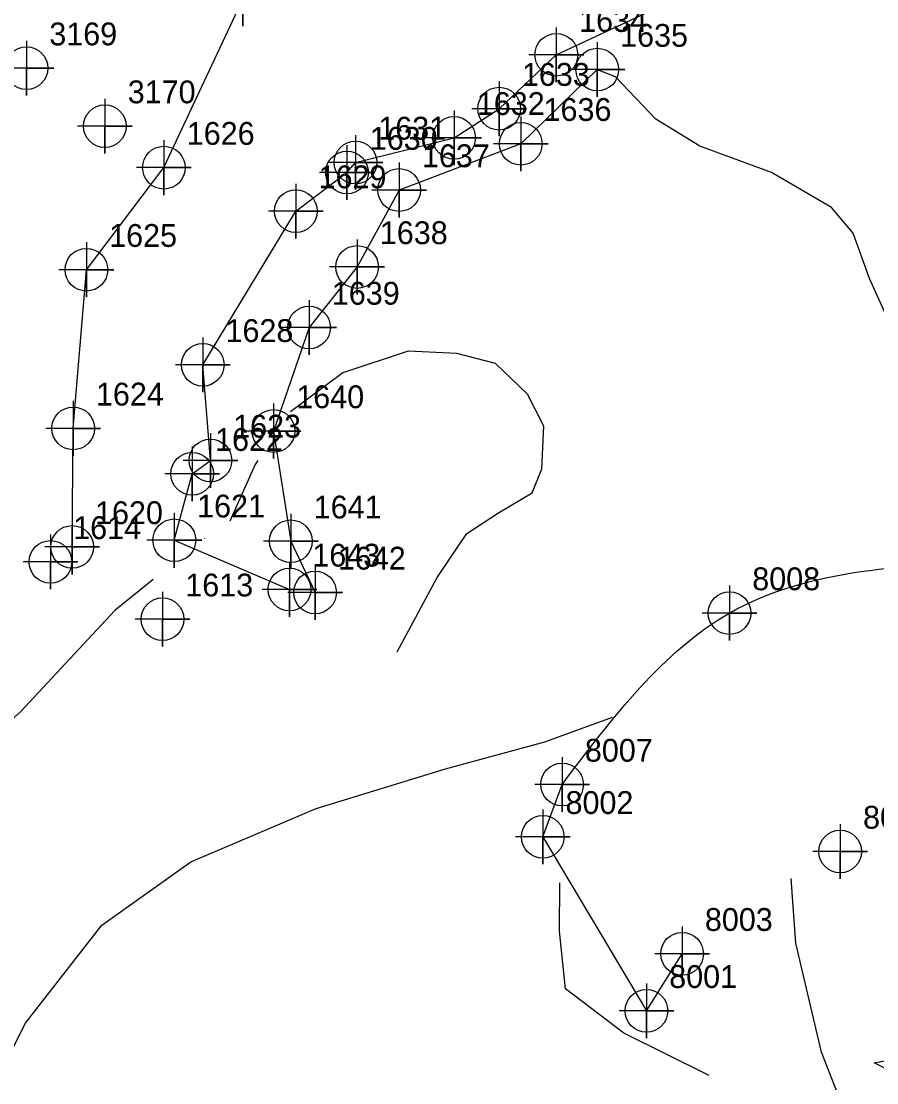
# Model space of a CAD drawing. Extents: x 2062781 to 2066835, y 358981 to 366501.
# Drawn here: x 2064156.3 to 2064250, y 361856.4 to 361972.7 of the extents above; entities that cross this region are included whole.
import ezdxf

# ---------------------------------------------------------------- set-up
doc = ezdxf.new("R2010")
doc.units = 0
for name, color, linetype in [('Exist Building Cogo Number', 7, 'Continuous'), ('Exist Building Cogo Point CELL', 7, 'Continuous'), ('Exist DTM Breakline', 7, 'Continuous'), ('Exist DTM Breakline Cogo Number', 7, 'Continuous'), ('Exist DTM Breakline Cogo Point CELL', 7, 'Continuous'), ('Exist DTM Regular Point CELL', 7, 'Continuous'), ('Exist DTM Regular Point Cogo Number', 7, 'Continuous'), ('Exist DTM Ridgeline', 7, 'Continuous'), ('Exist DTM Ridgeline Cogo Number', 7, 'Continuous'), ('Exist DTM Ridgeline Cogo Point CELL', 7, 'Continuous'), ('PH Exist DTM Breakline', 7, 'Continuous'), ('PH Exist DTM Point', 7, 'Continuous')]:
    doc.layers.add(name, color=color, linetype=linetype)

msp = doc.modelspace()

# ---------------------------------------------------------------- linework, layer by layer
at = {"layer": 'Exist Building Cogo Point CELL'}
for points in [[(2064233.88, 361910.89), (2064233.88, 361904.89), (2064233.88, 361907.89), (2064236.88, 361907.89), (2064230.88, 361907.89)], [(2064233.88, 361910.89), (2064233.88, 361904.89), (2064233.88, 361907.89), (2064236.88, 361907.89), (2064230.88, 361907.89)], [(2064233.88, 361910.89), (2064233.88, 361904.89), (2064233.88, 361907.89), (2064236.88, 361907.89), (2064230.88, 361907.89)], [(2064215.54, 361892.11), (2064215.54, 361886.11), (2064215.54, 361889.11), (2064218.54, 361889.11), (2064212.54, 361889.11)], [(2064215.54, 361892.11), (2064215.54, 361886.11), (2064215.54, 361889.11), (2064218.54, 361889.11), (2064212.54, 361889.11)], [(2064215.54, 361892.11), (2064215.54, 361886.11), (2064215.54, 361889.11), (2064218.54, 361889.11), (2064212.54, 361889.11)], [(2064213.42, 361886.38), (2064213.42, 361880.38), (2064213.42, 361883.38), (2064216.42, 361883.38), (2064210.42, 361883.38)], [(2064213.42, 361886.38), (2064213.42, 361880.38), (2064213.42, 361883.38), (2064216.42, 361883.38), (2064210.42, 361883.38)], [(2064213.42, 361886.38), (2064213.42, 361880.38), (2064213.42, 361883.38), (2064216.42, 361883.38), (2064210.42, 361883.38)], [(2064246.02, 361884.77), (2064246.02, 361878.77), (2064246.02, 361881.77), (2064249.02, 361881.77), (2064243.02, 361881.77)], [(2064246.02, 361884.77), (2064246.02, 361878.77), (2064246.02, 361881.77), (2064249.02, 361881.77), (2064243.02, 361881.77)], [(2064246.02, 361884.77), (2064246.02, 361878.77), (2064246.02, 361881.77), (2064249.02, 361881.77), (2064243.02, 361881.77)], [(2064228.69, 361873.57), (2064228.69, 361867.57), (2064228.69, 361870.57), (2064231.69, 361870.57), (2064225.69, 361870.57)], [(2064228.69, 361873.57), (2064228.69, 361867.57), (2064228.69, 361870.57), (2064231.69, 361870.57), (2064225.69, 361870.57)], [(2064228.69, 361873.57), (2064228.69, 361867.57), (2064228.69, 361870.57), (2064231.69, 361870.57), (2064225.69, 361870.57)], [(2064224.78, 361867.32), (2064224.78, 361861.32), (2064224.78, 361864.32), (2064227.78, 361864.32), (2064221.78, 361864.32)], [(2064224.78, 361867.32), (2064224.78, 361861.32), (2064224.78, 361864.32), (2064227.78, 361864.32), (2064221.78, 361864.32)], [(2064224.78, 361867.32), (2064224.78, 361861.32), (2064224.78, 361864.32), (2064227.78, 361864.32), (2064221.78, 361864.32)]]:
    msp.add_lwpolyline(points, dxfattribs=at)
for centre in [(2064233.88, 361907.89), (2064233.88, 361907.89), (2064233.88, 361907.89), (2064215.54, 361889.11), (2064215.54, 361889.11), (2064215.54, 361889.11), (2064213.42, 361883.38), (2064213.42, 361883.38), (2064213.42, 361883.38), (2064246.02, 361881.77), (2064246.02, 361881.77), (2064246.02, 361881.77), (2064228.69, 361870.57), (2064228.69, 361870.57), (2064228.69, 361870.57), (2064224.78, 361864.32), (2064224.78, 361864.32), (2064224.78, 361864.32)]:
    msp.add_circle(centre, 2.34, dxfattribs=at)
at = {"layer": 'Exist DTM Breakline'}
for p, q in [((2064214.91, 361969.05), (2064225.1, 361973.79)), ((2064213.42, 361883.38), (2064215.54, 361889.11)), ((2064224.78, 361864.32), (2064228.69, 361870.57))]:
    msp.add_line(p, q, dxfattribs=at)
for points in [[(2064173.05, 361915.86), (2064175.01, 361923.15), (2064177, 361924.61), (2064176.16, 361935.08), (2064186.36, 361951.92), (2064191.97, 361956.14), (2064192.9, 361957.25), (2064203.7, 361959.95), (2064208.64, 361963.14), (2064214.91, 361969.05)], [(2064173.05, 361915.86), (2064185.67, 361910.48)], [(2064213.42, 361883.38), (2064224.78, 361864.32)]]:
    msp.add_lwpolyline(points, dxfattribs=at)
msp.add_spline([(2064215.54, 361889.11), (2064233.88, 361907.89), (2064264.5, 361913.6)], degree=3, dxfattribs=at)
at = {"layer": 'Exist DTM Breakline Cogo Point CELL'}
for points in [[(2064214.91, 361972.05), (2064214.91, 361966.05), (2064214.91, 361969.05), (2064217.91, 361969.05), (2064211.91, 361969.05)], [(2064214.91, 361972.05), (2064214.91, 361966.05), (2064214.91, 361969.05), (2064217.91, 361969.05), (2064211.91, 361969.05)], [(2064214.91, 361972.05), (2064214.91, 361966.05), (2064214.91, 361969.05), (2064217.91, 361969.05), (2064211.91, 361969.05)], [(2064208.64, 361966.14), (2064208.64, 361960.14), (2064208.64, 361963.14), (2064211.64, 361963.14), (2064205.64, 361963.14)], [(2064208.64, 361966.14), (2064208.64, 361960.14), (2064208.64, 361963.14), (2064211.64, 361963.14), (2064205.64, 361963.14)], [(2064208.64, 361966.14), (2064208.64, 361960.14), (2064208.64, 361963.14), (2064211.64, 361963.14), (2064205.64, 361963.14)], [(2064203.7, 361962.95), (2064203.7, 361956.95), (2064203.7, 361959.95), (2064206.7, 361959.95), (2064200.7, 361959.95)], [(2064203.7, 361962.95), (2064203.7, 361956.95), (2064203.7, 361959.95), (2064206.7, 361959.95), (2064200.7, 361959.95)], [(2064203.7, 361962.95), (2064203.7, 361956.95), (2064203.7, 361959.95), (2064206.7, 361959.95), (2064200.7, 361959.95)], [(2064192.9, 361960.25), (2064192.9, 361954.25), (2064192.9, 361957.25), (2064195.9, 361957.25), (2064189.9, 361957.25)], [(2064192.9, 361960.25), (2064192.9, 361954.25), (2064192.9, 361957.25), (2064195.9, 361957.25), (2064189.9, 361957.25)], [(2064192.9, 361960.25), (2064192.9, 361954.25), (2064192.9, 361957.25), (2064195.9, 361957.25), (2064189.9, 361957.25)], [(2064191.97, 361959.14), (2064191.97, 361953.14), (2064191.97, 361956.14), (2064194.97, 361956.14), (2064188.97, 361956.14)], [(2064191.97, 361959.14), (2064191.97, 361953.14), (2064191.97, 361956.14), (2064194.97, 361956.14), (2064188.97, 361956.14)], [(2064191.97, 361959.14), (2064191.97, 361953.14), (2064191.97, 361956.14), (2064194.97, 361956.14), (2064188.97, 361956.14)], [(2064186.36, 361954.92), (2064186.36, 361948.92), (2064186.36, 361951.92), (2064189.36, 361951.92), (2064183.36, 361951.92)], [(2064186.36, 361954.92), (2064186.36, 361948.92), (2064186.36, 361951.92), (2064189.36, 361951.92), (2064183.36, 361951.92)], [(2064186.36, 361954.92), (2064186.36, 361948.92), (2064186.36, 361951.92), (2064189.36, 361951.92), (2064183.36, 361951.92)], [(2064176.16, 361938.08), (2064176.16, 361932.08), (2064176.16, 361935.08), (2064179.16, 361935.08), (2064173.16, 361935.08)], [(2064176.16, 361938.08), (2064176.16, 361932.08), (2064176.16, 361935.08), (2064179.16, 361935.08), (2064173.16, 361935.08)], [(2064176.16, 361938.08), (2064176.16, 361932.08), (2064176.16, 361935.08), (2064179.16, 361935.08), (2064173.16, 361935.08)], [(2064177, 361927.61), (2064177, 361921.61), (2064177, 361924.61), (2064180, 361924.61), (2064174, 361924.61)], [(2064177, 361927.61), (2064177, 361921.61), (2064177, 361924.61), (2064180, 361924.61), (2064174, 361924.61)], [(2064177, 361927.61), (2064177, 361921.61), (2064177, 361924.61), (2064180, 361924.61), (2064174, 361924.61)], [(2064175.01, 361926.15), (2064175.01, 361920.15), (2064175.01, 361923.15), (2064178.01, 361923.15), (2064172.01, 361923.15)], [(2064175.01, 361926.15), (2064175.01, 361920.15), (2064175.01, 361923.15), (2064178.01, 361923.15), (2064172.01, 361923.15)], [(2064175.01, 361926.15), (2064175.01, 361920.15), (2064175.01, 361923.15), (2064178.01, 361923.15), (2064172.01, 361923.15)], [(2064173.05, 361918.86), (2064173.05, 361912.86), (2064173.05, 361915.86), (2064176.05, 361915.86), (2064170.05, 361915.86)], [(2064173.05, 361918.86), (2064173.05, 361912.86), (2064173.05, 361915.86), (2064176.05, 361915.86), (2064170.05, 361915.86)], [(2064173.05, 361918.86), (2064173.05, 361912.86), (2064173.05, 361915.86), (2064176.05, 361915.86), (2064170.05, 361915.86)], [(2064185.67, 361913.48), (2064185.67, 361907.48), (2064185.67, 361910.48), (2064188.67, 361910.48), (2064182.67, 361910.48)], [(2064185.67, 361913.48), (2064185.67, 361907.48), (2064185.67, 361910.48), (2064188.67, 361910.48), (2064182.67, 361910.48)], [(2064185.67, 361913.48), (2064185.67, 361907.48), (2064185.67, 361910.48), (2064188.67, 361910.48), (2064182.67, 361910.48)]]:
    msp.add_lwpolyline(points, dxfattribs=at)
for centre in [(2064214.91, 361969.05), (2064214.91, 361969.05), (2064214.91, 361969.05), (2064208.64, 361963.14), (2064208.64, 361963.14), (2064208.64, 361963.14), (2064203.7, 361959.95), (2064203.7, 361959.95), (2064203.7, 361959.95), (2064192.9, 361957.25), (2064192.9, 361957.25), (2064192.9, 361957.25), (2064191.97, 361956.14), (2064191.97, 361956.14), (2064191.97, 361956.14), (2064186.36, 361951.92), (2064186.36, 361951.92), (2064186.36, 361951.92), (2064176.16, 361935.08), (2064176.16, 361935.08), (2064176.16, 361935.08), (2064177, 361924.61), (2064177, 361924.61), (2064177, 361924.61), (2064175.01, 361923.15), (2064175.01, 361923.15), (2064175.01, 361923.15), (2064173.05, 361915.86), (2064173.05, 361915.86), (2064173.05, 361915.86), (2064185.67, 361910.48), (2064185.67, 361910.48), (2064185.67, 361910.48)]:
    msp.add_circle(centre, 2.34, dxfattribs=at)
at = {"layer": 'Exist DTM Regular Point CELL'}
for points in [[(2064156.85, 361970.58), (2064156.85, 361964.58), (2064156.85, 361967.58), (2064159.85, 361967.58), (2064153.85, 361967.58)], [(2064165.44, 361964.23), (2064165.44, 361958.23), (2064165.44, 361961.23), (2064168.44, 361961.23), (2064162.44, 361961.23)], [(2064159.47, 361916.49), (2064159.47, 361910.49), (2064159.47, 361913.49), (2064162.47, 361913.49), (2064156.47, 361913.49)], [(2064171.75, 361910.21), (2064171.75, 361904.21), (2064171.75, 361907.21), (2064174.75, 361907.21), (2064168.75, 361907.21)]]:
    msp.add_lwpolyline(points, dxfattribs=at)
for centre in [(2064156.85, 361967.58), (2064165.44, 361961.23), (2064159.47, 361913.49), (2064171.75, 361907.21)]:
    msp.add_circle(centre, 2.34, dxfattribs=at)
at = {"layer": 'Exist DTM Ridgeline'}
msp.add_line((2064219.4, 361967.42), (2064221.37, 361966.68), dxfattribs=at)
for points in [[(2064171.91, 361956.68), (2064180.57, 361975.17)], [(2064219.4, 361967.42), (2064211.01, 361959.3), (2064197.68, 361954.23), (2064193.07, 361945.8), (2064187.81, 361939.17), (2064183.91, 361927.83), (2064185.82, 361915.75), (2064188.47, 361910.15)], [(2064161.86, 361915.13), (2064161.96, 361928.12), (2064163.41, 361945.5), (2064171.91, 361956.68)]]:
    msp.add_lwpolyline(points, dxfattribs=at)
at = {"layer": 'Exist DTM Ridgeline Cogo Point CELL'}
for points in [[(2064180.57, 361978.17), (2064180.57, 361972.17), (2064180.57, 361975.17), (2064183.57, 361975.17), (2064177.57, 361975.17)], [(2064180.57, 361978.17), (2064180.57, 361972.17), (2064180.57, 361975.17), (2064183.57, 361975.17), (2064177.57, 361975.17)], [(2064180.57, 361978.17), (2064180.57, 361972.17), (2064180.57, 361975.17), (2064183.57, 361975.17), (2064177.57, 361975.17)], [(2064219.4, 361970.42), (2064219.4, 361964.42), (2064219.4, 361967.42), (2064222.4, 361967.42), (2064216.4, 361967.42)], [(2064219.4, 361970.42), (2064219.4, 361964.42), (2064219.4, 361967.42), (2064222.4, 361967.42), (2064216.4, 361967.42)], [(2064219.4, 361970.42), (2064219.4, 361964.42), (2064219.4, 361967.42), (2064222.4, 361967.42), (2064216.4, 361967.42)], [(2064211.01, 361962.3), (2064211.01, 361956.3), (2064211.01, 361959.3), (2064214.01, 361959.3), (2064208.01, 361959.3)], [(2064211.01, 361962.3), (2064211.01, 361956.3), (2064211.01, 361959.3), (2064214.01, 361959.3), (2064208.01, 361959.3)], [(2064211.01, 361962.3), (2064211.01, 361956.3), (2064211.01, 361959.3), (2064214.01, 361959.3), (2064208.01, 361959.3)], [(2064171.91, 361959.68), (2064171.91, 361953.68), (2064171.91, 361956.68), (2064174.91, 361956.68), (2064168.91, 361956.68)], [(2064171.91, 361959.68), (2064171.91, 361953.68), (2064171.91, 361956.68), (2064174.91, 361956.68), (2064168.91, 361956.68)], [(2064171.91, 361959.68), (2064171.91, 361953.68), (2064171.91, 361956.68), (2064174.91, 361956.68), (2064168.91, 361956.68)], [(2064197.68, 361957.23), (2064197.68, 361951.23), (2064197.68, 361954.23), (2064200.68, 361954.23), (2064194.68, 361954.23)], [(2064197.68, 361957.23), (2064197.68, 361951.23), (2064197.68, 361954.23), (2064200.68, 361954.23), (2064194.68, 361954.23)], [(2064197.68, 361957.23), (2064197.68, 361951.23), (2064197.68, 361954.23), (2064200.68, 361954.23), (2064194.68, 361954.23)], [(2064193.07, 361948.8), (2064193.07, 361942.8), (2064193.07, 361945.8), (2064196.07, 361945.8), (2064190.07, 361945.8)], [(2064193.07, 361948.8), (2064193.07, 361942.8), (2064193.07, 361945.8), (2064196.07, 361945.8), (2064190.07, 361945.8)], [(2064193.07, 361948.8), (2064193.07, 361942.8), (2064193.07, 361945.8), (2064196.07, 361945.8), (2064190.07, 361945.8)], [(2064163.41, 361948.5), (2064163.41, 361942.5), (2064163.41, 361945.5), (2064166.41, 361945.5), (2064160.41, 361945.5)], [(2064163.41, 361948.5), (2064163.41, 361942.5), (2064163.41, 361945.5), (2064166.41, 361945.5), (2064160.41, 361945.5)], [(2064163.41, 361948.5), (2064163.41, 361942.5), (2064163.41, 361945.5), (2064166.41, 361945.5), (2064160.41, 361945.5)], [(2064187.81, 361942.17), (2064187.81, 361936.17), (2064187.81, 361939.17), (2064190.81, 361939.17), (2064184.81, 361939.17)], [(2064187.81, 361942.17), (2064187.81, 361936.17), (2064187.81, 361939.17), (2064190.81, 361939.17), (2064184.81, 361939.17)], [(2064187.81, 361942.17), (2064187.81, 361936.17), (2064187.81, 361939.17), (2064190.81, 361939.17), (2064184.81, 361939.17)], [(2064161.96, 361931.12), (2064161.96, 361925.12), (2064161.96, 361928.12), (2064164.96, 361928.12), (2064158.96, 361928.12)], [(2064161.96, 361931.12), (2064161.96, 361925.12), (2064161.96, 361928.12), (2064164.96, 361928.12), (2064158.96, 361928.12)], [(2064161.96, 361931.12), (2064161.96, 361925.12), (2064161.96, 361928.12), (2064164.96, 361928.12), (2064158.96, 361928.12)], [(2064183.91, 361930.83), (2064183.91, 361924.83), (2064183.91, 361927.83), (2064186.91, 361927.83), (2064180.91, 361927.83)], [(2064183.91, 361930.83), (2064183.91, 361924.83), (2064183.91, 361927.83), (2064186.91, 361927.83), (2064180.91, 361927.83)], [(2064183.91, 361930.83), (2064183.91, 361924.83), (2064183.91, 361927.83), (2064186.91, 361927.83), (2064180.91, 361927.83)], [(2064185.82, 361918.75), (2064185.82, 361912.75), (2064185.82, 361915.75), (2064188.82, 361915.75), (2064182.82, 361915.75)], [(2064185.82, 361918.75), (2064185.82, 361912.75), (2064185.82, 361915.75), (2064188.82, 361915.75), (2064182.82, 361915.75)], [(2064185.82, 361918.75), (2064185.82, 361912.75), (2064185.82, 361915.75), (2064188.82, 361915.75), (2064182.82, 361915.75)], [(2064161.86, 361918.13), (2064161.86, 361912.13), (2064161.86, 361915.13), (2064164.86, 361915.13), (2064158.86, 361915.13)], [(2064161.86, 361918.13), (2064161.86, 361912.13), (2064161.86, 361915.13), (2064164.86, 361915.13), (2064158.86, 361915.13)], [(2064161.86, 361918.13), (2064161.86, 361912.13), (2064161.86, 361915.13), (2064164.86, 361915.13), (2064158.86, 361915.13)], [(2064188.47, 361913.15), (2064188.47, 361907.15), (2064188.47, 361910.15), (2064191.47, 361910.15), (2064185.47, 361910.15)], [(2064188.47, 361913.15), (2064188.47, 361907.15), (2064188.47, 361910.15), (2064191.47, 361910.15), (2064185.47, 361910.15)], [(2064188.47, 361913.15), (2064188.47, 361907.15), (2064188.47, 361910.15), (2064191.47, 361910.15), (2064185.47, 361910.15)]]:
    msp.add_lwpolyline(points, dxfattribs=at)
for centre in [(2064219.4, 361967.42), (2064219.4, 361967.42), (2064219.4, 361967.42), (2064211.01, 361959.3), (2064211.01, 361959.3), (2064211.01, 361959.3), (2064171.91, 361956.68), (2064171.91, 361956.68), (2064171.91, 361956.68), (2064197.68, 361954.23), (2064197.68, 361954.23), (2064197.68, 361954.23), (2064163.41, 361945.5), (2064163.41, 361945.5), (2064163.41, 361945.5), (2064193.07, 361945.8), (2064193.07, 361945.8), (2064193.07, 361945.8), (2064187.81, 361939.17), (2064187.81, 361939.17), (2064187.81, 361939.17), (2064161.96, 361928.12), (2064161.96, 361928.12), (2064161.96, 361928.12), (2064183.91, 361927.83), (2064183.91, 361927.83), (2064183.91, 361927.83), (2064161.86, 361915.13), (2064161.86, 361915.13), (2064161.86, 361915.13), (2064185.82, 361915.75), (2064185.82, 361915.75), (2064185.82, 361915.75), (2064188.47, 361910.15), (2064188.47, 361910.15), (2064188.47, 361910.15)]:
    msp.add_circle(centre, 2.34, dxfattribs=at)
at = {"layer": 'PH Exist DTM Breakline'}
for points in [[(2064347.08, 361899.76), (2064335.27, 361906.48), (2064323.58, 361907.86), (2064312.7, 361908.49), (2064297.61, 361916.01), (2064287.51, 361922.76), (2064282.79, 361926.44), (2064274.67, 361928.18), (2064265.74, 361929.27), (2064257.51, 361933.27), (2064251.47, 361939.6), (2064249.24, 361944.52), (2064247.44, 361949.52), (2064245.07, 361952.31), (2064238.5, 361956.15), (2064230.65, 361959.03), (2064225.83, 361962), (2064221.37, 361966.68)], [(2064197.46, 361903.66), (2064201.86, 361911.77), (2064205.09, 361916.62), (2064208.59, 361918.88), (2064212.26, 361921.06), (2064213.33, 361923.7), (2064213.55, 361928.36), (2064211.76, 361931.88), (2064208.23, 361935.21), (2064204.01, 361936.31), (2064198.69, 361936.57), (2064191.5, 361934.21), (2064185.77, 361929.94)], [(2064182.19, 361924.6), (2064181.91, 361924.18), (2064179.13, 361917.96)], [(2064176.37, 361916.09), (2064176.34, 361916.06)], [(2064170.73, 361911.56), (2064166.53, 361908.18), (2064156.19, 361897.07), (2064146.84, 361888.8), (2064141.42, 361883.92), (2064134.1, 361876.3), (2064129.49, 361870.67)], [(2064084.81, 361744.46), (2064096.35, 361767.5), (2064110.2, 361790.69), (2064120.37, 361810.99), (2064130.95, 361828.02), (2064140.91, 361839.56), (2064150.75, 361851.05), (2064156.71, 361862.93), (2064165.11, 361873.71), (2064174.86, 361880.63), (2064188.6, 361886.48), (2064202.77, 361890.84), (2064213.64, 361893.77), (2064221.06, 361896.49)], [(2064231.66, 361857.25), (2064222.29, 361861.86), (2064215.9, 361866.73), (2064215.26, 361873.05), (2064215.28, 361878.32)], [(2064246.06, 361854.45), (2064243.98, 361859.8), (2064241.17, 361871.74), (2064240.65, 361878.83)], [(2064285.59, 361840.27), (2064253.87, 361856.55), (2064249.73, 361858.62), (2064255.73, 361859.77)]]:
    msp.add_lwpolyline(points, dxfattribs=at)
at = {"layer": 'PH Exist DTM Point'}
for p, q in [((2064230.65, 361970.27), (2064230.65, 361970.27)), ((2064211.7, 361963.15), (2064211.7, 361963.15)), ((2064210.65, 361950.27), (2064210.65, 361950.27)), ((2064230.65, 361950.27), (2064230.65, 361950.27)), ((2064194.61, 361944.69), (2064194.61, 361944.69)), ((2064230.65, 361930.27), (2064230.65, 361930.27)), ((2064192.23, 361928.22), (2064192.23, 361928.22)), ((2064207.58, 361927.46), (2064207.58, 361927.46)), ((2064248.49, 361917.4), (2064248.49, 361917.4)), ((2064190.65, 361910.27), (2064190.65, 361910.27)), ((2064210.65, 361910.27), (2064210.65, 361910.27)), ((2064230.65, 361910.27), (2064230.65, 361910.27)), ((2064188.74, 361894.75), (2064188.74, 361894.75)), ((2064170.65, 361890.27), (2064170.65, 361890.27)), ((2064230.65, 361890.27), (2064230.65, 361890.27)), ((2064210.8, 361888.14), (2064210.8, 361888.14)), ((2064210.96, 361872.01), (2064210.96, 361872.01)), ((2064170.65, 361870.27), (2064170.65, 361870.27)), ((2064190.65, 361870.27), (2064190.65, 361870.27)), ((2064230.65, 361870.27), (2064230.65, 361870.27))]:
    msp.add_line(p, q, dxfattribs=at)

# ---------------------------------------------------------------- texts
at = {"layer": 'Exist Building Cogo Number'}
for s, p in [('8008', (2064236.38, 361910.39)), ('8008', (2064236.38, 361910.39)), ('8008', (2064236.38, 361910.39)), ('8007', (2064218.04, 361891.61)), ('8007', (2064218.04, 361891.61)), ('8007', (2064218.04, 361891.61)), ('8002', (2064215.92, 361885.88)), ('8002', (2064215.92, 361885.88)), ('8002', (2064215.92, 361885.88)), ('8004', (2064248.52, 361884.27)), ('8004', (2064248.52, 361884.27)), ('8004', (2064248.52, 361884.27)), ('8003', (2064231.19, 361873.07)), ('8003', (2064231.19, 361873.07)), ('8003', (2064231.19, 361873.07)), ('8001', (2064227.28, 361866.82)), ('8001', (2064227.28, 361866.82)), ('8001', (2064227.28, 361866.82))]:
    msp.add_text(s, height=2.5, dxfattribs=at).set_placement(p)
at = {"layer": 'Exist DTM Breakline Cogo Number'}
for s, p in [('1634', (2064217.41, 361971.55)), ('1634', (2064217.41, 361971.55)), ('1634', (2064217.41, 361971.55)), ('1633', (2064211.14, 361965.64)), ('1633', (2064211.14, 361965.64)), ('1633', (2064211.14, 361965.64)), ('1632', (2064206.2, 361962.45)), ('1632', (2064206.2, 361962.45)), ('1632', (2064206.2, 361962.45)), ('1631', (2064195.4, 361959.75)), ('1631', (2064195.4, 361959.75)), ('1631', (2064195.4, 361959.75)), ('1630', (2064194.47, 361958.64)), ('1630', (2064194.47, 361958.64)), ('1630', (2064194.47, 361958.64)), ('1629', (2064188.86, 361954.42)), ('1629', (2064188.86, 361954.42)), ('1629', (2064188.86, 361954.42)), ('1628', (2064178.66, 361937.58)), ('1628', (2064178.66, 361937.58)), ('1628', (2064178.66, 361937.58)), ('1623', (2064179.5, 361927.11)), ('1623', (2064179.5, 361927.11)), ('1623', (2064179.5, 361927.11)), ('1622', (2064177.51, 361925.65)), ('1622', (2064177.51, 361925.65)), ('1622', (2064177.51, 361925.65)), ('1621', (2064175.55, 361918.36)), ('1621', (2064175.55, 361918.36)), ('1621', (2064175.55, 361918.36)), ('1643', (2064188.17, 361912.98)), ('1643', (2064188.17, 361912.98)), ('1643', (2064188.17, 361912.98))]:
    msp.add_text(s, height=2.5, dxfattribs=at).set_placement(p)
at = {"layer": 'Exist DTM Regular Point Cogo Number'}
for s, p in [('3169', (2064159.35, 361970.08)), ('3169', (2064159.35, 361970.08)), ('3169', (2064159.35, 361970.08)), ('3170', (2064167.94, 361963.73)), ('3170', (2064167.94, 361963.73)), ('3170', (2064167.94, 361963.73)), ('1614', (2064161.97, 361915.99)), ('1614', (2064161.97, 361915.99)), ('1614', (2064161.97, 361915.99)), ('1613', (2064174.25, 361909.71)), ('1613', (2064174.25, 361909.71)), ('1613', (2064174.25, 361909.71))]:
    msp.add_text(s, height=2.5, dxfattribs=at).set_placement(p)
at = {"layer": 'Exist DTM Ridgeline Cogo Number'}
for s, p in [('1635', (2064221.9, 361969.92)), ('1635', (2064221.9, 361969.92)), ('1635', (2064221.9, 361969.92)), ('1636', (2064213.51, 361961.8)), ('1636', (2064213.51, 361961.8)), ('1636', (2064213.51, 361961.8)), ('1626', (2064174.41, 361959.18)), ('1626', (2064174.41, 361959.18)), ('1626', (2064174.41, 361959.18)), ('1637', (2064200.18, 361956.73)), ('1637', (2064200.18, 361956.73)), ('1637', (2064200.18, 361956.73)), ('1625', (2064165.91, 361948)), ('1625', (2064165.91, 361948)), ('1625', (2064165.91, 361948)), ('1638', (2064195.57, 361948.3)), ('1638', (2064195.57, 361948.3)), ('1638', (2064195.57, 361948.3)), ('1639', (2064190.31, 361941.67)), ('1639', (2064190.31, 361941.67)), ('1639', (2064190.31, 361941.67)), ('1624', (2064164.46, 361930.62)), ('1624', (2064164.46, 361930.62)), ('1624', (2064164.46, 361930.62)), ('1640', (2064186.41, 361930.33)), ('1640', (2064186.41, 361930.33)), ('1640', (2064186.41, 361930.33)), ('1620', (2064164.36, 361917.63)), ('1620', (2064164.36, 361917.63)), ('1620', (2064164.36, 361917.63)), ('1641', (2064188.32, 361918.25)), ('1641', (2064188.32, 361918.25)), ('1641', (2064188.32, 361918.25)), ('1642', (2064190.97, 361912.65)), ('1642', (2064190.97, 361912.65)), ('1642', (2064190.97, 361912.65))]:
    msp.add_text(s, height=2.5, dxfattribs=at).set_placement(p)

doc.saveas('drawing.dxf')
